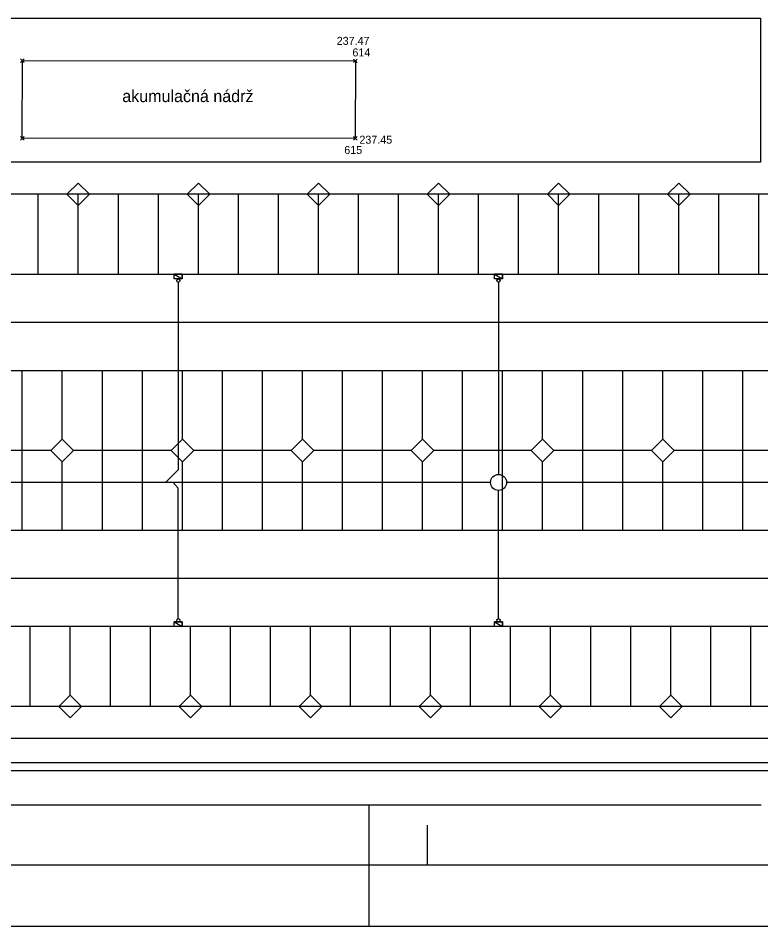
# Model space of a CAD drawing. Extents: x -264205 to -263659, y -1242401 to -1242060.
# Drawn here: x -263900.8 to -263854.4, y -1242311.7 to -1242255 of the extents above; entities that cross this region are included whole.
import ezdxf

# ---------------------------------------------------------------- set-up
doc = ezdxf.new("R2010")
doc.units = 0
for name, color, linetype in [('BOD_CISLO', 7, 'Continuous'), ('BOD_SYMBOL', 7, 'Continuous'), ('BOD_VYSKA', 7, 'Continuous'), ('KFA_SO_10-1_AKUMULACNA_NADRZ', 7, 'Continuous'), ('OBRUBNIKY_KOMUNIKACIE_PROJEKT', 7, 'Continuous'), ('POPIS', 7, 'Continuous'), ('RAM_NA_TLAC_12xA4_1-250', 7, 'Continuous'), ('SITUACIA_DSP_2D', 7, 'Continuous'), ('TDZ_VODOROVNE_PROJEKT', 7, 'Continuous')]:
    doc.layers.add(name, color=color, linetype=linetype)

msp = doc.modelspace()

# ---------------------------------------------------------------- linework, layer by layer
at = {"layer": 'BOD_SYMBOL'}
for p, q in [((-263900.672, -1242257.741), (-263900.451, -1242257.519)), ((-263900.451, -1242257.741), (-263900.672, -1242257.519)), ((-263879.873, -1242257.755), (-263879.652, -1242257.534)), ((-263879.652, -1242257.755), (-263879.873, -1242257.534)), ((-263900.679, -1242262.6), (-263900.458, -1242262.38)), ((-263900.458, -1242262.6), (-263900.679, -1242262.38)), ((-263879.883, -1242262.595), (-263879.662, -1242262.373)), ((-263879.662, -1242262.595), (-263879.883, -1242262.373))]:
    msp.add_line(p, q, dxfattribs=at)
at = {"layer": 'KFA_SO_10-1_AKUMULACNA_NADRZ'}
msp.add_lwpolyline([(-263900.562, -1242257.63), (-263879.763, -1242257.644), (-263879.773, -1242262.484), (-263900.568, -1242262.49)], close=True, dxfattribs=at)
at = {"layer": 'OBRUBNIKY_KOMUNIKACIE_PROJEKT'}
for p, q in [((-263901.868, -1242254.982), (-263854.468, -1242254.985)), ((-263854.468, -1242254.985), (-263854.468, -1242263.985)), ((-263854.468, -1242263.985), (-263917.08, -1242263.982)), ((-263897.775, -1242265.986), (-263897.068, -1242265.279)), ((-263897.775, -1242265.986), (-263897.068, -1242265.279)), ((-263897.068, -1242265.279), (-263896.361, -1242265.986)), ((-263897.068, -1242265.279), (-263896.361, -1242265.986)), ((-263890.275, -1242265.986), (-263889.568, -1242265.279)), ((-263889.568, -1242265.279), (-263888.861, -1242265.986)), ((-263882.775, -1242265.986), (-263882.068, -1242265.279)), ((-263882.068, -1242265.279), (-263881.361, -1242265.986)), ((-263875.275, -1242265.986), (-263874.568, -1242265.279)), ((-263874.568, -1242265.279), (-263873.861, -1242265.986)), ((-263867.775, -1242265.986), (-263867.068, -1242265.279)), ((-263867.068, -1242265.279), (-263866.361, -1242265.986)), ((-263860.275, -1242265.986), (-263859.568, -1242265.279)), ((-263859.568, -1242265.279), (-263858.861, -1242265.986)), ((-263822.79, -1242265.987), (-263917.08, -1242265.983)), ((-263897.068, -1242266.694), (-263897.775, -1242265.986)), ((-263897.068, -1242266.694), (-263897.775, -1242265.986)), ((-263896.361, -1242265.986), (-263897.068, -1242266.694)), ((-263896.361, -1242265.986), (-263897.068, -1242266.694)), ((-263889.568, -1242266.694), (-263890.275, -1242265.986)), ((-263888.861, -1242265.986), (-263889.568, -1242266.694)), ((-263882.068, -1242266.694), (-263882.775, -1242265.986)), ((-263881.361, -1242265.986), (-263882.068, -1242266.694)), ((-263874.568, -1242266.694), (-263875.275, -1242265.986)), ((-263873.861, -1242265.986), (-263874.568, -1242266.694)), ((-263867.068, -1242266.694), (-263867.775, -1242265.986)), ((-263866.361, -1242265.986), (-263867.068, -1242266.694)), ((-263859.568, -1242266.694), (-263860.275, -1242265.986)), ((-263858.861, -1242265.986), (-263859.568, -1242266.694)), ((-263917.578, -1242270.983), (-263822.79, -1242270.982)), ((-263917.08, -1242276.982), (-263822.79, -1242276.982)), ((-263898.775, -1242281.982), (-263898.068, -1242281.275)), ((-263898.068, -1242281.275), (-263897.361, -1242281.982)), ((-263891.275, -1242281.982), (-263890.568, -1242281.275)), ((-263891.275, -1242281.982), (-263890.568, -1242281.275)), ((-263890.568, -1242281.275), (-263889.861, -1242281.982)), ((-263890.568, -1242281.275), (-263889.861, -1242281.982)), ((-263883.775, -1242281.982), (-263883.068, -1242281.275)), ((-263883.068, -1242281.275), (-263882.361, -1242281.982)), ((-263876.275, -1242281.982), (-263875.568, -1242281.275)), ((-263875.568, -1242281.275), (-263874.861, -1242281.982)), ((-263868.775, -1242281.982), (-263868.068, -1242281.275)), ((-263868.068, -1242281.275), (-263867.361, -1242281.982)), ((-263861.275, -1242281.982), (-263860.568, -1242281.275)), ((-263860.568, -1242281.275), (-263859.861, -1242281.982)), ((-263898.068, -1242282.689), (-263898.775, -1242281.982)), ((-263897.361, -1242281.982), (-263898.068, -1242282.689)), ((-263890.568, -1242282.689), (-263891.275, -1242281.982)), ((-263890.568, -1242282.689), (-263891.275, -1242281.982)), ((-263889.861, -1242281.982), (-263890.568, -1242282.689)), ((-263889.861, -1242281.982), (-263890.568, -1242282.689)), ((-263883.068, -1242282.689), (-263883.775, -1242281.982)), ((-263882.361, -1242281.982), (-263883.068, -1242282.689)), ((-263875.568, -1242282.689), (-263876.275, -1242281.982)), ((-263874.861, -1242281.982), (-263875.568, -1242282.689)), ((-263868.068, -1242282.689), (-263868.775, -1242281.982)), ((-263867.361, -1242281.982), (-263868.068, -1242282.689)), ((-263860.568, -1242282.689), (-263861.275, -1242281.982)), ((-263859.861, -1242281.982), (-263860.568, -1242282.689)), ((-263822.79, -1242286.982), (-263917.08, -1242286.982)), ((-263822.79, -1242292.982), (-263917.08, -1242292.982)), ((-263898.275, -1242297.982), (-263897.568, -1242297.275)), ((-263897.568, -1242297.275), (-263896.861, -1242297.982)), ((-263890.775, -1242297.982), (-263890.068, -1242297.275)), ((-263890.775, -1242297.982), (-263890.068, -1242297.275)), ((-263890.068, -1242297.275), (-263889.361, -1242297.982)), ((-263890.068, -1242297.275), (-263889.361, -1242297.982)), ((-263883.275, -1242297.982), (-263882.568, -1242297.275)), ((-263882.568, -1242297.275), (-263881.861, -1242297.982)), ((-263875.775, -1242297.982), (-263875.068, -1242297.275)), ((-263875.068, -1242297.275), (-263874.361, -1242297.982)), ((-263868.275, -1242297.982), (-263867.568, -1242297.275)), ((-263867.568, -1242297.275), (-263866.861, -1242297.982)), ((-263860.775, -1242297.982), (-263860.068, -1242297.275)), ((-263860.068, -1242297.275), (-263859.361, -1242297.982)), ((-263822.79, -1242297.982), (-263917.08, -1242297.982)), ((-263897.568, -1242298.689), (-263898.275, -1242297.982)), ((-263896.861, -1242297.982), (-263897.568, -1242298.689)), ((-263890.068, -1242298.689), (-263890.775, -1242297.982)), ((-263890.068, -1242298.689), (-263890.775, -1242297.982)), ((-263889.361, -1242297.982), (-263890.068, -1242298.689)), ((-263889.361, -1242297.982), (-263890.068, -1242298.689)), ((-263882.568, -1242298.689), (-263883.275, -1242297.982)), ((-263881.861, -1242297.982), (-263882.568, -1242298.689)), ((-263875.068, -1242298.689), (-263875.775, -1242297.982)), ((-263874.361, -1242297.982), (-263875.068, -1242298.689)), ((-263867.568, -1242298.689), (-263868.275, -1242297.982)), ((-263866.861, -1242297.982), (-263867.568, -1242298.689)), ((-263860.068, -1242298.689), (-263860.775, -1242297.982)), ((-263859.361, -1242297.982), (-263860.068, -1242298.689)), ((-263822.79, -1242299.982), (-263918.049, -1242299.982)), ((-263914.08, -1242301.482), (-263822.79, -1242301.482))]:
    msp.add_line(p, q, dxfattribs=at)
at = {"layer": 'RAM_NA_TLAC_12xA4_1-250'}
msp.add_line((-263875.29, -1242305.386), (-263875.29, -1242307.886), dxfattribs=at)
msp.add_lwpolyline([(-263980.29, -1242085.136), (-263770.29, -1242085.136), (-263770.29, -1242307.886), (-263980.29, -1242307.886)], close=True, dxfattribs=at)
at = {"layer": 'SITUACIA_DSP_2D'}
for p, q in [((-263901.868, -1242254.982), (-263854.468, -1242254.985)), ((-263854.468, -1242254.985), (-263854.468, -1242263.985)), ((-263854.468, -1242263.985), (-263917.08, -1242263.982)), ((-263897.775, -1242265.986), (-263897.068, -1242265.279)), ((-263897.775, -1242265.986), (-263897.068, -1242265.279)), ((-263897.068, -1242265.279), (-263896.361, -1242265.986)), ((-263897.068, -1242265.279), (-263896.361, -1242265.986)), ((-263890.275, -1242265.986), (-263889.568, -1242265.279)), ((-263889.568, -1242265.279), (-263888.861, -1242265.986)), ((-263882.775, -1242265.986), (-263882.068, -1242265.279)), ((-263882.068, -1242265.279), (-263881.361, -1242265.986)), ((-263875.275, -1242265.986), (-263874.568, -1242265.279)), ((-263874.568, -1242265.279), (-263873.861, -1242265.986)), ((-263867.775, -1242265.986), (-263867.068, -1242265.279)), ((-263867.068, -1242265.279), (-263866.361, -1242265.986)), ((-263860.275, -1242265.986), (-263859.568, -1242265.279)), ((-263859.568, -1242265.279), (-263858.861, -1242265.986)), ((-263897.068, -1242266.693), (-263897.775, -1242265.986)), ((-263897.068, -1242266.693), (-263897.775, -1242265.986)), ((-263896.361, -1242265.986), (-263897.068, -1242266.693)), ((-263896.361, -1242265.986), (-263897.068, -1242266.693)), ((-263889.568, -1242266.693), (-263890.275, -1242265.986)), ((-263888.861, -1242265.986), (-263889.568, -1242266.693)), ((-263882.068, -1242266.693), (-263882.775, -1242265.986)), ((-263881.361, -1242265.986), (-263882.068, -1242266.693)), ((-263874.568, -1242266.693), (-263875.275, -1242265.986)), ((-263873.861, -1242265.986), (-263874.568, -1242266.693)), ((-263867.068, -1242266.693), (-263867.775, -1242265.986)), ((-263866.361, -1242265.986), (-263867.068, -1242266.693)), ((-263859.568, -1242266.693), (-263860.275, -1242265.986)), ((-263858.861, -1242265.986), (-263859.568, -1242266.693)), ((-263891.074, -1242270.983), (-263890.574, -1242270.983)), ((-263891.074, -1242271.273), (-263891.074, -1242270.983)), ((-263891.074, -1242270.983), (-263890.574, -1242271.273)), ((-263891.074, -1242270.983), (-263890.574, -1242271.273)), ((-263890.574, -1242270.983), (-263891.074, -1242270.983)), ((-263890.574, -1242271.273), (-263891.074, -1242271.273)), ((-263890.824, -1242271.473), (-263890.824, -1242283.187)), ((-263890.574, -1242270.983), (-263890.574, -1242271.273)), ((-263890.574, -1242271.273), (-263890.574, -1242270.983)), ((-263871.074, -1242270.983), (-263870.574, -1242270.983)), ((-263871.074, -1242271.273), (-263871.074, -1242270.983)), ((-263871.074, -1242270.983), (-263870.574, -1242271.273)), ((-263871.074, -1242270.983), (-263870.574, -1242271.273)), ((-263870.574, -1242270.983), (-263871.074, -1242270.983)), ((-263870.574, -1242271.273), (-263871.074, -1242271.273)), ((-263870.824, -1242271.473), (-263870.824, -1242283.482)), ((-263870.574, -1242270.983), (-263870.574, -1242271.273)), ((-263870.574, -1242271.273), (-263870.574, -1242270.983)), ((-263898.775, -1242281.982), (-263898.068, -1242281.275)), ((-263898.068, -1242281.275), (-263897.361, -1242281.982)), ((-263891.275, -1242281.982), (-263890.568, -1242281.275)), ((-263891.275, -1242281.982), (-263890.568, -1242281.275)), ((-263890.568, -1242281.275), (-263889.861, -1242281.982)), ((-263890.568, -1242281.275), (-263889.861, -1242281.982)), ((-263883.775, -1242281.982), (-263883.068, -1242281.275)), ((-263883.068, -1242281.275), (-263882.361, -1242281.982)), ((-263876.275, -1242281.982), (-263875.568, -1242281.275)), ((-263875.568, -1242281.275), (-263874.861, -1242281.982)), ((-263868.775, -1242281.982), (-263868.068, -1242281.275)), ((-263868.068, -1242281.275), (-263867.361, -1242281.982)), ((-263861.275, -1242281.982), (-263860.568, -1242281.275)), ((-263860.568, -1242281.275), (-263859.861, -1242281.982)), ((-263898.068, -1242282.689), (-263898.775, -1242281.982)), ((-263897.361, -1242281.982), (-263898.068, -1242282.689)), ((-263890.568, -1242282.689), (-263891.275, -1242281.982)), ((-263890.568, -1242282.689), (-263891.275, -1242281.982)), ((-263889.861, -1242281.982), (-263890.568, -1242282.689)), ((-263889.861, -1242281.982), (-263890.568, -1242282.689)), ((-263883.068, -1242282.689), (-263883.775, -1242281.982)), ((-263882.361, -1242281.982), (-263883.068, -1242282.689)), ((-263875.568, -1242282.689), (-263876.275, -1242281.982)), ((-263874.861, -1242281.982), (-263875.568, -1242282.689)), ((-263868.068, -1242282.689), (-263868.775, -1242281.982)), ((-263867.361, -1242281.982), (-263868.068, -1242282.689)), ((-263860.568, -1242282.689), (-263861.275, -1242281.982)), ((-263859.861, -1242281.982), (-263860.568, -1242282.689)), ((-263890.824, -1242283.187), (-263891.619, -1242283.982)), ((-263871.324, -1242283.982), (-263903.413, -1242283.982)), ((-263890.824, -1242284.343), (-263891.149, -1242283.982)), ((-263822.79, -1242283.982), (-263870.324, -1242283.982)), ((-263822.79, -1242283.982), (-263870.324, -1242283.982)), ((-263890.824, -1242292.492), (-263890.824, -1242284.343)), ((-263870.824, -1242292.492), (-263870.824, -1242284.482)), ((-263891.074, -1242292.693), (-263890.574, -1242292.693)), ((-263891.074, -1242292.983), (-263891.074, -1242292.693)), ((-263891.074, -1242292.693), (-263890.574, -1242292.983)), ((-263891.074, -1242292.693), (-263890.574, -1242292.983)), ((-263890.574, -1242292.693), (-263891.074, -1242292.693)), ((-263890.574, -1242292.983), (-263891.074, -1242292.983)), ((-263890.574, -1242292.693), (-263890.574, -1242292.983)), ((-263890.574, -1242292.983), (-263890.574, -1242292.693)), ((-263871.074, -1242292.693), (-263870.574, -1242292.693)), ((-263871.074, -1242292.983), (-263871.074, -1242292.693)), ((-263871.074, -1242292.693), (-263870.574, -1242292.983)), ((-263871.074, -1242292.693), (-263870.574, -1242292.983)), ((-263870.574, -1242292.693), (-263871.074, -1242292.693)), ((-263870.574, -1242292.983), (-263871.074, -1242292.983)), ((-263870.574, -1242292.693), (-263870.574, -1242292.983)), ((-263870.574, -1242292.983), (-263870.574, -1242292.693)), ((-263898.275, -1242297.982), (-263897.568, -1242297.275)), ((-263897.568, -1242297.275), (-263896.861, -1242297.982)), ((-263890.775, -1242297.982), (-263890.068, -1242297.275)), ((-263890.775, -1242297.982), (-263890.068, -1242297.275)), ((-263890.068, -1242297.275), (-263889.361, -1242297.982)), ((-263890.068, -1242297.275), (-263889.361, -1242297.982)), ((-263883.275, -1242297.982), (-263882.568, -1242297.275)), ((-263882.568, -1242297.275), (-263881.861, -1242297.982)), ((-263875.775, -1242297.982), (-263875.068, -1242297.275)), ((-263875.068, -1242297.275), (-263874.361, -1242297.982)), ((-263868.275, -1242297.982), (-263867.568, -1242297.275)), ((-263867.568, -1242297.275), (-263866.861, -1242297.982)), ((-263860.775, -1242297.982), (-263860.068, -1242297.275)), ((-263860.068, -1242297.275), (-263859.361, -1242297.982)), ((-263822.79, -1242297.982), (-263917.08, -1242297.982)), ((-263897.568, -1242298.689), (-263898.275, -1242297.982)), ((-263896.861, -1242297.982), (-263897.568, -1242298.689)), ((-263890.068, -1242298.689), (-263890.775, -1242297.982)), ((-263890.068, -1242298.689), (-263890.775, -1242297.982)), ((-263889.361, -1242297.982), (-263890.068, -1242298.689)), ((-263889.361, -1242297.982), (-263890.068, -1242298.689)), ((-263882.568, -1242298.689), (-263883.275, -1242297.982)), ((-263881.861, -1242297.982), (-263882.568, -1242298.689)), ((-263875.068, -1242298.689), (-263875.775, -1242297.982)), ((-263874.361, -1242297.982), (-263875.068, -1242298.689)), ((-263867.568, -1242298.689), (-263868.275, -1242297.982)), ((-263866.861, -1242297.982), (-263867.568, -1242298.689)), ((-263860.068, -1242298.689), (-263860.775, -1242297.982)), ((-263859.361, -1242297.982), (-263860.068, -1242298.689)), ((-263822.79, -1242299.982), (-263918.049, -1242299.982)), ((-263914.08, -1242301.482), (-263822.79, -1242301.482)), ((-263854.415, -1242304.147), (-263903.413, -1242304.147)), ((-263878.913, -1242311.742), (-263878.913, -1242304.147))]:
    msp.add_line(p, q, dxfattribs=at)
for centre, radius in [((-263890.824, -1242271.373), 0.1), ((-263870.824, -1242271.373), 0.1), ((-263870.824, -1242283.982), 0.5), ((-263890.824, -1242292.592), 0.1), ((-263870.824, -1242292.592), 0.1)]:
    msp.add_circle(centre, radius, dxfattribs=at)
at = {"layer": 'TDZ_VODOROVNE_PROJEKT'}
for p, q in [((-263899.568, -1242270.982), (-263899.568, -1242265.982)), ((-263897.068, -1242270.982), (-263897.068, -1242265.982)), ((-263894.568, -1242270.982), (-263894.568, -1242265.982)), ((-263892.068, -1242270.982), (-263892.068, -1242265.982)), ((-263889.568, -1242270.982), (-263889.568, -1242265.982)), ((-263887.068, -1242270.982), (-263887.068, -1242265.982)), ((-263884.568, -1242270.982), (-263884.568, -1242265.982)), ((-263882.068, -1242270.982), (-263882.068, -1242265.982)), ((-263879.568, -1242270.982), (-263879.568, -1242265.982)), ((-263877.068, -1242270.982), (-263877.068, -1242265.982)), ((-263874.568, -1242270.982), (-263874.568, -1242265.982)), ((-263872.068, -1242270.982), (-263872.068, -1242265.982)), ((-263869.568, -1242270.982), (-263869.568, -1242265.982)), ((-263867.068, -1242270.982), (-263867.068, -1242265.982)), ((-263864.568, -1242270.982), (-263864.568, -1242265.982)), ((-263862.068, -1242270.982), (-263862.068, -1242265.982)), ((-263859.568, -1242270.982), (-263859.568, -1242265.982)), ((-263857.068, -1242270.982), (-263857.068, -1242265.982)), ((-263854.568, -1242270.982), (-263854.568, -1242265.982)), ((-263822.79, -1242273.982), (-263917.477, -1242273.982)), ((-263900.568, -1242281.982), (-263900.568, -1242276.982)), ((-263898.068, -1242281.275), (-263898.068, -1242276.982)), ((-263895.568, -1242281.982), (-263895.568, -1242276.982)), ((-263893.068, -1242281.982), (-263893.068, -1242276.982)), ((-263890.568, -1242281.275), (-263890.568, -1242276.982)), ((-263888.068, -1242281.982), (-263888.068, -1242276.982)), ((-263885.568, -1242281.982), (-263885.568, -1242276.982)), ((-263883.068, -1242281.275), (-263883.068, -1242276.982)), ((-263880.568, -1242281.982), (-263880.568, -1242276.982)), ((-263878.068, -1242281.982), (-263878.068, -1242276.982)), ((-263875.568, -1242281.275), (-263875.568, -1242276.982)), ((-263873.068, -1242281.982), (-263873.068, -1242276.982)), ((-263870.568, -1242281.982), (-263870.568, -1242276.982)), ((-263868.068, -1242281.275), (-263868.068, -1242276.982)), ((-263865.568, -1242281.982), (-263865.568, -1242276.982)), ((-263863.068, -1242281.982), (-263863.068, -1242276.982)), ((-263860.568, -1242281.275), (-263860.568, -1242276.982)), ((-263858.068, -1242281.982), (-263858.068, -1242276.982)), ((-263855.568, -1242281.982), (-263855.568, -1242276.982)), ((-263898.775, -1242281.982), (-263917.08, -1242281.982)), ((-263900.568, -1242286.982), (-263900.568, -1242281.982)), ((-263891.275, -1242281.982), (-263897.361, -1242281.982)), ((-263895.568, -1242286.982), (-263895.568, -1242281.982)), ((-263893.068, -1242286.982), (-263893.068, -1242281.982)), ((-263883.775, -1242281.982), (-263889.861, -1242281.982)), ((-263888.068, -1242286.982), (-263888.068, -1242281.982)), ((-263885.568, -1242286.982), (-263885.568, -1242281.982)), ((-263876.275, -1242281.982), (-263882.361, -1242281.982)), ((-263880.568, -1242286.982), (-263880.568, -1242281.982)), ((-263878.068, -1242286.982), (-263878.068, -1242281.982)), ((-263868.775, -1242281.982), (-263874.861, -1242281.982)), ((-263873.068, -1242286.982), (-263873.068, -1242281.982)), ((-263870.568, -1242286.982), (-263870.568, -1242281.982)), ((-263861.275, -1242281.982), (-263867.361, -1242281.982)), ((-263865.568, -1242286.982), (-263865.568, -1242281.982)), ((-263863.068, -1242286.982), (-263863.068, -1242281.982)), ((-263853.775, -1242281.982), (-263859.861, -1242281.982)), ((-263858.068, -1242286.982), (-263858.068, -1242281.982)), ((-263855.568, -1242286.982), (-263855.568, -1242281.982)), ((-263898.068, -1242286.982), (-263898.068, -1242282.689)), ((-263890.568, -1242286.982), (-263890.568, -1242282.689)), ((-263883.068, -1242286.982), (-263883.068, -1242282.689)), ((-263875.568, -1242286.982), (-263875.568, -1242282.689)), ((-263868.068, -1242286.982), (-263868.068, -1242282.689)), ((-263860.568, -1242286.982), (-263860.568, -1242282.689)), ((-263822.79, -1242289.994), (-263917.477, -1242289.994)), ((-263900.068, -1242297.982), (-263900.068, -1242292.982)), ((-263897.568, -1242297.275), (-263897.568, -1242292.982)), ((-263895.068, -1242297.982), (-263895.068, -1242292.982)), ((-263892.568, -1242297.982), (-263892.568, -1242292.982)), ((-263890.068, -1242297.275), (-263890.068, -1242292.982)), ((-263887.568, -1242297.982), (-263887.568, -1242292.982)), ((-263885.068, -1242297.982), (-263885.068, -1242292.982)), ((-263882.568, -1242297.275), (-263882.568, -1242292.982)), ((-263880.068, -1242297.982), (-263880.068, -1242292.982)), ((-263877.568, -1242297.982), (-263877.568, -1242292.982)), ((-263875.068, -1242297.275), (-263875.068, -1242292.982)), ((-263872.568, -1242297.982), (-263872.568, -1242292.982)), ((-263870.068, -1242297.982), (-263870.068, -1242292.982)), ((-263867.568, -1242297.275), (-263867.568, -1242292.982)), ((-263865.068, -1242297.982), (-263865.068, -1242292.982)), ((-263862.568, -1242297.982), (-263862.568, -1242292.982)), ((-263860.068, -1242297.275), (-263860.068, -1242292.982)), ((-263857.568, -1242297.982), (-263857.568, -1242292.982)), ((-263855.068, -1242297.982), (-263855.068, -1242292.982)), ((-263913.857, -1242301.982), (-263822.79, -1242301.982)), ((-263842.661, -1242311.732), (-263980.94, -1242311.732))]:
    msp.add_line(p, q, dxfattribs=at)

# ---------------------------------------------------------------- texts
at = {"layer": 'BOD_CISLO'}
for s, p in [('614', (-263879.948, -1242257.371)), ('615', (-263880.458, -1242263.467))]:
    msp.add_text(s, height=0.5, dxfattribs=at).set_placement(p)
at = {"layer": 'BOD_VYSKA'}
for s, p in [('237.47', (-263880.928, -1242256.649)), ('237.45', (-263879.512, -1242262.824))]:
    msp.add_text(s, height=0.5, dxfattribs=at).set_placement(p)
at = {"layer": 'POPIS'}
msp.add_text('akumulačná nádrž', height=0.75, dxfattribs=at).set_placement((-263894.322, -1242260.225))

doc.saveas('drawing.dxf')
